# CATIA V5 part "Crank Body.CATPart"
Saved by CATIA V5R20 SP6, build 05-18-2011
Part number: Crank Body
Bounding box of the stored display mesh (mm): x -38.5 to 8.5, y -13.73 to 13.73, z -35 to 6
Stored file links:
  E:\#03 University\#02 영남 이공대\#01 2021\#02 여름 방학\#01 Documents\K-Move Page02 ASD02\Crank Body.CATPart

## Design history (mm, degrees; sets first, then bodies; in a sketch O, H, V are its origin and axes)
Set1 "Reference Data"
  Point1 "Center Point": (0, 0, 0)
  Plane1 "Plane.1(XY Offset=-15mm)": type Offset, RefPlane xy-plane, Offset 15, reversed
  Plane2 "Plane.2(Solid Side Offset=30mm)": type Offset, RefPlane start face of Pad1, Offset 30, reversed
Body1 (main body)
  Body2
    Sketch1 on yz-plane, origin (0, 0, 0), H (0, 1, 0), V (0, 0, 1)
      arc A1 centre (0, 0) radius 6 from (6, 0) to (-6, 0) ccw
      arc A2 centre (0, -15) radius 20 from (-15, -28.2288) to (15, -28.2288) ccw
      point P1 (0, -15)
      point P2 (-6, 0)
      line L1 (-6, 0) -> (-6, -23.0326)
      point P3 (-6, -23.0326)
      line L2 (-6, -23.0326) -> (-15, -28.2288)
      point P4 (-15, -28.2288)
      point P5 (6, -23.0326)
      line L3 (6, 0) -> (6, -23.0326)
      line L4 (6, -23.0326) -> (15, -28.2288)
      point P7 (15, -28.2288)
      reference intersected line E1 through (0, -15) direction (-1, 0) from Plane1
      distance L3 L1 = 12
      angle L2 L4 = 120
      distance P4 P7 = 30
      radius A2 = 20
      coincidence: P1 V, P2 A1, P2 H, P4 A2, P4 L2, P2 L1, P1 E1
      tangency: L1 A1
      symmetry: P3 P5 V, L1 L3 V, L2 L4 V
    Pad1: profile Sketch1, direction (1, 0, 0), length 8.5, mirrored extent
    Fillet1: radius 2, on edge [face of Pad1 from Sketch1.L3 | face of Pad1 from Sketch1.L4]; edge [face of Pad1 from Sketch1.L2 | face of Pad1 from Sketch1.L1]; edge [face of Pad1 from Sketch1.A2 | face of Pad1 from Sketch1.L2]; edge [face of Pad1 from Sketch1.L4 | face of Pad1 from Sketch1.A2]
  Assemble1: tool Body2
  Body3 "Pocket Body"
    Sketch2 on yz-plane, origin (0, 0, 0), H (0, 1, 0), V (0, 0, 1)
      arc A1 centre (0, 0) radius 6 from (-6, 0) to (6, 0) ccw
      radius A1 = 6
    Pad2: profile Sketch2, direction (1, 0, 0), length 5.5, mirrored extent
  Remove1: tool Body3
  Body4 "Hole Body"
    Sketch3 on yz-plane, origin (0, 0, 0), H (0, 1, 0), V (0, 0, 1)
      circle A1 centre (0, 0) radius 4
      projected arc E1 centre (0, 0) radius 6 from (6, 0) to (-6, 0) ccw from edge [face of Pad1 from Sketch1.A1 | end face of Pad1]
      projected circle E2 centre (0, 0) radius 6 from edge [face of Pad1 from Sketch1.A1 | end face of Pad1]
      point P1 (6, 0)
      point P3 (6, 0)
      radius A1 = 4
      coincidence: P1 P3
    Pad3: profile Sketch3, direction (1, 0, 0), length 3.5, mirrored extent
  Remove2: tool Body4
  Body5 "Hole Boss Body"
    Sketch4 on yz-plane, origin (0, 0, 0), H (0, 1, 0), V (0, 0, 1)
      circle A1 centre (0, -15) radius 4
      point P1 (0, -15)
      reference intersected line E1 through (0, -15) direction (-1, 0) from Plane1
      radius A1 = 4
      coincidence: P1 V, P1 E1
    Pad4: profile Sketch4, direction (-1, 0, 0), up to Plane2, opposite side length -8.5
    Body6 "Key Hole Body"
      Sketch5 on zx-plane, origin (0, 0, 0), H (-1, 0, 0), V (0, 0, 1)
        construction line L1 (23.7462, -15) -> (38.3022, -15)
        reference intersected line E1 through (0, -15) direction (-1, 0) from Plane1
        line L2 (38.5, -13.5) -> (26.5, -13.5)
        arc A1 centre (26.5, -15) radius 1.5 from (26.5, -13.5) to (26.5, -16.5) ccw
        point P5 (26.5, -15)
        line L3 (26.5, -16.5) -> (38.5, -16.5)
        line L4 (38.5, -16.5) -> (38.5, -13.5)
        reference intersected line E2 through (38.5, 0) direction (0, -1) from Plane2
        distance L2 L3 = 3
        distance L4 P5 = 12
        horizontal: L1 H, L2 H
        coincidence: L1 E1, E2 L4
        tangency: A1 L2, L3 A1
        vertical: L4 V
        symmetry: L2 L3 L1
      Pad5: profile Sketch5, direction (0, 1, 0), length 5, opposite side length -2.2
    Remove3: tool Body6
  Assemble2: tool Body5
